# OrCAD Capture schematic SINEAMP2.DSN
size A; title: Sine Wave BJT Amplifier; rev: A; company: EMA Design Automation; note: EMA-12345678; note: 225 Tech Park Dr; note: Rochester, NY, 14623
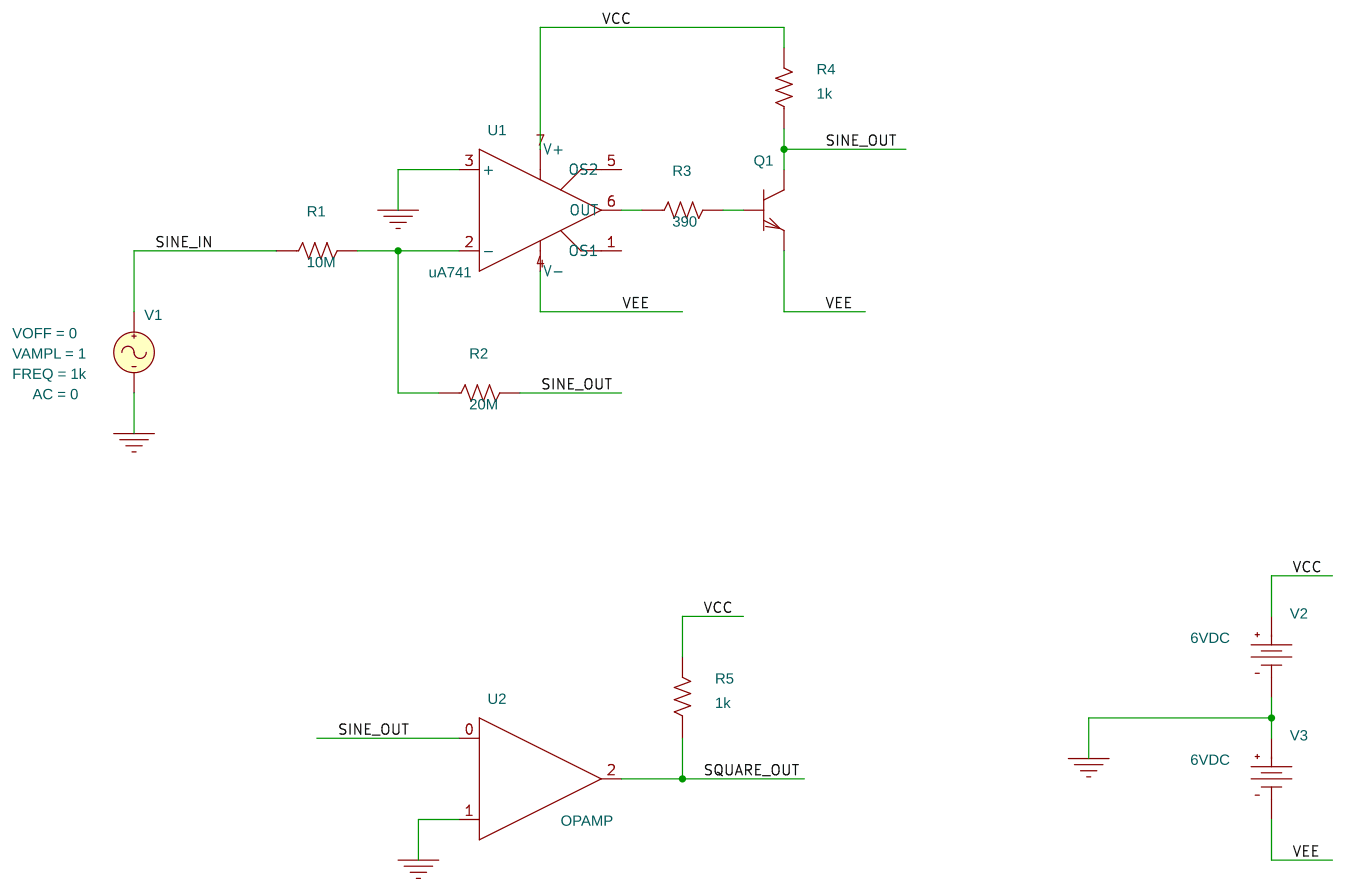
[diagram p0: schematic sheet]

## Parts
Q1  QbreakN
R1  10M  [AXRC05]
R2  20M  [AXRC05]
R3  390  [AXRC05]
R4  1k  [AXRC05]
R5  1k  [AXRC05]
U1  uA741  [DIP1008W300L450]
U2  OPAMP
V1  VSIN
V2  VDC
V3  VDC

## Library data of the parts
Q1 = QbreakN: PSpiceTemplate: Q^@REFDES  %c %b %e @MODEL ?AREA/@AREA/
R1-R5 = R
U1 = uA741
U2 = OPAMP
V1 = VSIN: AC: 0; AppProp: Sine$Voltage$0$-1; DC: 0; FREQ: 1k; VAMPL: 1; VOFF: 0
V2 V3 = VDC: DC: 6VDC

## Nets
VCC: R4.2 R5.2 U1.7(V+) V2.0(+)
VEE: Q1.2(e) U1.4(V-) V3.1(-)
0: U1.3(+) U2.1(-) V1.2(-) V2.1(-) V3.0(+)
SINE_IN: R1.1 V1.1(+)
SINE_OUT: Q1.1(c) R2.2 R4.1 U2.0(+)
SQUARE_OUT: R5.1 U2.2(OUT)
N00219: R1.2 R2.1 U1.2(-)
N00342: R3.1 U1.6(OUT)
N00350: Q1.0(b) R3.2

Not connected (* = marked no-connect by the designer): U1 1(OS1) 5(OS2)
